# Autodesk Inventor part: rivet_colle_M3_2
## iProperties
Created: 2011-01
Part Number: rivet_colle_M3_2
Document SubType Name: Modeling
Designer: eric
Density: 1 g/cm^3
Mass: 0.0620465 g
Surface Area: 1.40979 cm^2
Volume: 0.0620465 cm^3
Author: eric
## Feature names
1. Base1
